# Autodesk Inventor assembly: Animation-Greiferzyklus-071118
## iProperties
Manager: Dr.-Ing. Roland Schröder
Company: www.Das-Entwicklungsbuero.de
Created: 2007-11
Part Number: Animation-Greiferzyklus-071118
Project: 11308
Document SubType Name: Assembly
Designer: rsc
Engineer: Dr.-Ing. Roland Schröder
Oberflächen: Ra 3,2
Toleranzen: ISO 2768 - m
a: 17.000 oE
b: 10.000 mm
d: 34.000 mm
Author: rsc
